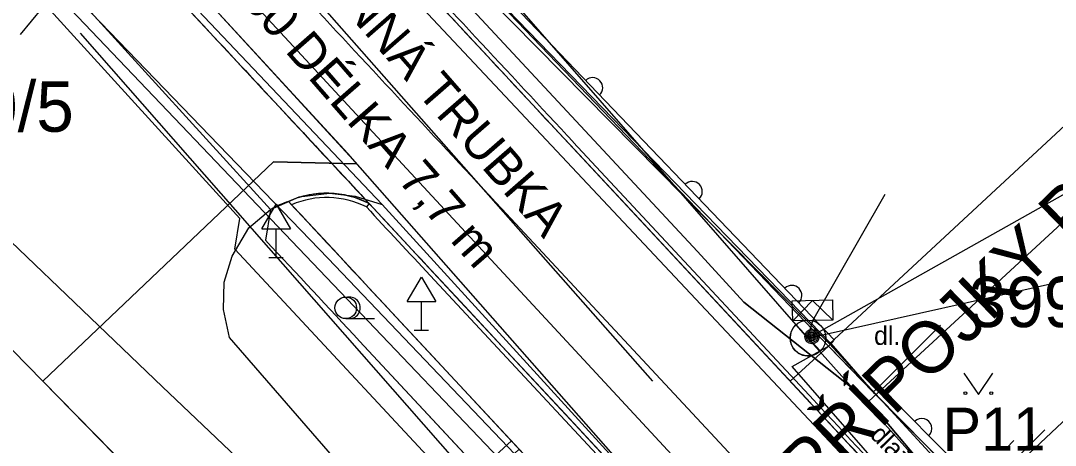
# Model space of a CAD drawing. Extents: x -643342 to -638635, y -1201752 to -1189948.
# Drawn here: x -639576.01 to -639540.06, y -1192560.69 to -1192545.93 of the extents above; entities that cross this region are included whole.
import ezdxf

# ---------------------------------------------------------------- set-up
doc = ezdxf.new("R2010")
doc.units = 0
for name, color, linetype in [('2', 7, 'Continuous'), ('42', 7, 'Continuous'), ('IS_EL_NN_NADZEMNÍ', 7, 'Continuous'), ('IS_EL_NN_PODZEMNÍ', 7, 'Continuous'), ('IS_PLYN_STL', 7, 'Continuous'), ('IS_TELEF_MISTNI_ZAMERENO', 7, 'Continuous'), ('IS_VODOVOD_VAS', 7, 'Continuous'), ('IS_VODOVOD_ZRUSENY', 7, 'Continuous'), ('K-HRANICE_KN', 7, 'Continuous'), ('K-ČÍSLA_PARCEL', 7, 'Continuous'), ('N-CHODNIK', 7, 'Continuous'), ('N-KAN_DEST_TRASA-NÁVRH', 7, 'Continuous'), ('N-OBVOD STAVBY 06', 7, 'Continuous'), ('N-OSA', 7, 'Continuous'), ('N-SILNICE', 7, 'Continuous'), ('N-SJEZDY', 7, 'Continuous'), ('N-SRAFY_PLOCHY', 7, 'Continuous'), ('N-SVAHOVÁNÍ', 7, 'Continuous'), ('tomaštík - Džuganovi - Vrstva 36', 7, 'Continuous'), ('Vrstva 46', 7, 'Continuous'), ('Z-hrany_a_čáry', 7, 'Continuous'), ('Z-popisy', 7, 'Continuous'), ('Z-sloupy', 7, 'Continuous'), ('Z-vchody_vjezdy', 7, 'Continuous'), ('Z-značky', 7, 'Continuous')]:
    doc.layers.add(name, color=color, linetype=linetype)

msp = doc.modelspace()

# ---------------------------------------------------------------- linework, layer by layer
at = {"layer": '42'}
msp.add_line((-639572.181, -1192537.888), (-639554.057, -1192558.462), dxfattribs=at)
at = {"layer": 'IS_EL_NN_NADZEMNÍ'}
for p, q in [((-639548.65, -1192556.96), (-639563.68, -1192539.76)), ((-639521.55, -1192587.25), (-639548.65, -1192556.96))]:
    msp.add_line(p, q, dxfattribs=at)
msp.add_lwpolyline([(-639547.781, -1192556.334), (-639549.18, -1192556.366), (-639549.196, -1192555.667), (-639547.797, -1192555.635)], close=True, dxfattribs=at)
for points in [[(-639547.781, -1192556.334), (-639548.496, -1192555.651), (-639549.18, -1192556.366)], [(-639549.063, -1192556.498), (-639548.222, -1192557.408)], [(-639548.222, -1192557.408), (-639549.063, -1192556.498)]]:
    msp.add_lwpolyline(points, dxfattribs=at)
msp.add_circle((-639548.65, -1192556.96), 0.62, dxfattribs=at)
for centre, radius, start, end in [((-639548.65, -1192556.96), 0.62, 131.8144, 312.7334), ((-639548.673, -1192556.986), 0.618, 315.9487, 316.8728)]:
    msp.add_arc(centre, radius, start, end, dxfattribs=at)
at = {"layer": 'IS_EL_NN_PODZEMNÍ'}
for p, q in [((-639548.65, -1192556.96), (-639533.97, -1192548.7)), ((-639548.48, -1192556.35), (-639545.97, -1192551.96)), ((-639548.65, -1192556.96), (-639532.15, -1192553.27)), ((-639548.65, -1192556.96), (-639548.48, -1192556.35))]:
    msp.add_line(p, q, dxfattribs=at)
at = {"layer": 'IS_PLYN_STL'}
msp.add_lwpolyline([(-639579.72, -1192550.39), (-639579.14, -1192550.94), (-639571.08, -1192558.66), (-639565.93, -1192563.54), (-639560.66, -1192567.58), (-639559.68, -1192568.38)], dxfattribs=at)
at = {"layer": 'IS_TELEF_MISTNI_ZAMERENO'}
for p, q in [((-639560.62, -1192545.22), (-639552.49, -1192553.95)), ((-639552.49, -1192553.95), (-639560.62, -1192545.22)), ((-639546.53, -1192559.15), (-639536.54, -1192549.92)), ((-639552.49, -1192553.95), (-639550.88, -1192555.71)), ((-639550.88, -1192555.71), (-639546.53, -1192559.15)), ((-639546.53, -1192559.15), (-639550.88, -1192555.71)), ((-639546.53, -1192559.15), (-639540.07, -1192566.82)), ((-639540.07, -1192566.82), (-639546.53, -1192559.15))]:
    msp.add_line(p, q, dxfattribs=at)
at = {"layer": 'IS_VODOVOD_VAS'}
for points in [[(-639574.178, -1192545), (-639565.32, -1192554.2), (-639544.196, -1192576.345), (-639543.991, -1192576.56), (-639543.73, -1192576.83), (-639534.504, -1192586.506), (-639531.24, -1192590.494), (-639527.133, -1192595.51), (-639522.796, -1192601.597), (-639522.77, -1192601.637), (-639518.91, -1192607.22), (-639515.881, -1192615.376)], [(-639575.085, -1192545.333), (-639575.259, -1192545.488), (-639576.018, -1192546.41)], [(-639574.504, -1192545.287), (-639565.62, -1192554.6), (-639534.876, -1192586.834), (-639527.527, -1192595.81), (-639523.229, -1192601.871), (-639519.29, -1192607.54), (-639519.07, -1192608.24), (-639516.818, -1192614.307), (-639515.63, -1192618.18), (-639513.05, -1192632.38), (-639511.6, -1192653.11)]]:
    msp.add_lwpolyline(points, dxfattribs=at)
at = {"layer": 'IS_VODOVOD_ZRUSENY'}
msp.add_lwpolyline([(-639573.944, -1192546.368), (-639550.08, -1192573.56), (-639545.32, -1192575.03), (-639544.04, -1192576.59), (-639530.53, -1192590.38), (-639522.03, -1192601.36), (-639515.23, -1192614.43)], dxfattribs=at)
at = {"layer": 'K-HRANICE_KN'}
for p, q in [((-639564.643, -1192550.549), (-639574.559, -1192539.749)), ((-639574.559, -1192539.749), (-639564.324, -1192550.911)), ((-639564.643, -1192550.549), (-639574.559, -1192539.749)), ((-639547.9, -1192557.16), (-639564.74, -1192540.08)), ((-639547.9, -1192557.16), (-639537.05, -1192547.08)), ((-639583.2, -1192550.31), (-639575.24, -1192558.46)), ((-639575.24, -1192558.46), (-639583.197, -1192550.313)), ((-639524.691, -1192595.875), (-639564.643, -1192550.549)), ((-639524.691, -1192595.875), (-639564.643, -1192550.549)), ((-639575.24, -1192558.46), (-639567.217, -1192550.837)), ((-639567.217, -1192550.837), (-639575.24, -1192558.46)), ((-639575.24, -1192558.46), (-639567.217, -1192550.837)), ((-639564.324, -1192550.911), (-639567.217, -1192550.837)), ((-639567.217, -1192550.837), (-639564.324, -1192550.911)), ((-639542.8, -1192562.7), (-639532.09, -1192552.6)), ((-639542.8, -1192562.7), (-639547.9, -1192557.16)), ((-639561.72, -1192572.25), (-639575.24, -1192558.46)), ((-639562.65, -1192571.27), (-639575.24, -1192558.46))]:
    msp.add_line(p, q, dxfattribs=at)
at = {"layer": 'N-CHODNIK'}
for p, q in [((-639547.94, -1192557.24), (-639564.59, -1192539.87)), ((-639563.902, -1192552.283), (-639563.994, -1192552.405)), ((-639563.132, -1192556.044), (-639554.775, -1192565.016)), ((-639547.94, -1192557.24), (-639549.267, -1192558.458)), ((-639549.267, -1192558.458), (-639547.94, -1192557.24)), ((-639546.38, -1192558.84), (-639547.94, -1192557.24)), ((-639542.746, -1192562.497), (-639546.38, -1192558.84))]:
    msp.add_line(p, q, dxfattribs=at)
for centre, radius, start, end in [((-639565.377, -1192555.154), 3.227, 62.8122, 114.2453), ((-639565.377, -1192555.154), 3.077, 63.2943, 113.2968), ((-632043.168, -1185549.151), 10278.444, 222.9480255, 222.977221)]:
    msp.add_arc(centre, radius, start, end, dxfattribs=at)
at = {"layer": 'N-KAN_DEST_TRASA-NÁVRH'}
msp.add_lwpolyline([(-639583.962, -1192528.01), (-639550.452, -1192564.184), (-639529.583, -1192588.026), (-639514.491, -1192612.048), (-639507.737, -1192644.326), (-639498.832, -1192694.254), (-639511.439, -1192713.331), (-639516.613, -1192716.507), (-639553.938, -1192703.739), (-639570.485, -1192701.616), (-639578.687, -1192703.18)], dxfattribs=at)
at = {"layer": 'N-OBVOD STAVBY 06'}
for points in [[(-639580.824, -1192520.961), (-639575.028, -1192527.69), (-639575.555, -1192528.126), (-639571.584, -1192532.34), (-639569.898, -1192532.101), (-639567.334, -1192531.011), (-639562.714, -1192535.496), (-639563.777, -1192537.334), (-639563.916, -1192537.749), (-639564.117, -1192538.572), (-639564.127, -1192539.047), (-639564.59, -1192539.87), (-639556.157, -1192548.58), (-639547.851, -1192557.152), (-639546.37, -1192558.85), (-639546.295, -1192558.925), (-639542.755, -1192562.507)], [(-639532.853, -1192592.991), (-639532.948, -1192593.015), (-639536.515, -1192588.213), (-639537.119, -1192588.308), (-639546.267, -1192578.054), (-639553.229, -1192570.356), (-639556.749, -1192566.564), (-639568.569, -1192553.875), (-639568.389, -1192552.802), (-639591.813, -1192527.078)]]:
    msp.add_lwpolyline(points, dxfattribs=at)
at = {"layer": 'N-OSA'}
msp.add_lwpolyline([(-639550.934, -1192561.438), (-639559.291, -1192552.466)], dxfattribs=at)
msp.add_arc((-632042.643, -1185548.663), 10273.911, 222.9214561, 222.9772243, dxfattribs=at)
at = {"layer": 'N-SILNICE'}
for p, q in [((-639556.912, -1192550.251), (-639548.555, -1192559.223)), ((-639548.557, -1192559.221), (-639556.912, -1192550.251)), ((-639556.803, -1192550.149), (-639548.446, -1192559.12)), ((-639561.778, -1192554.784), (-639553.421, -1192563.755)), ((-639561.669, -1192554.681), (-639553.312, -1192563.653))]:
    msp.add_line(p, q, dxfattribs=at)
for centre, radius, start, end in [((-632043.168, -1185549.151), 10269.944, 222.9214551, 222.977221), ((-632042.268, -1185548.314), 10271.173, 222.9214572, 222.9772255), ((-632043.168, -1185549.151), 10269.794, 222.9214551, 222.977221), ((-635904.087, -1189140.863), 5003.201, 222.848207, 222.911144), ((-632043.168, -1185549.151), 10276.444, 222.9214551, 222.977221), ((-632043.168, -1185549.151), 10276.594, 222.9591018, 222.977221), ((-640272.452, -1193234.69), 990.092, 42.727797, 43.018095), ((-640272.828, -1193235.039), 990.605, 42.727709, 43.018008), ((-640272.452, -1193234.69), 990.242, 42.727797, 43.018095)]:
    msp.add_arc(centre, radius, start, end, dxfattribs=at)
at = {"layer": 'N-SJEZDY'}
msp.add_line((-639590.66, -1192526.86), (-639567.322, -1192552.488), dxfattribs=at)
msp.add_arc((-639565.694, -1192555.36), 3.301, 107.7054, 119.5413, dxfattribs=at)
at = {"layer": 'N-SRAFY_PLOCHY'}
for p, q in [((-639590.66, -1192526.86), (-639567.322, -1192552.488)), ((-639547.94, -1192557.24), (-639564.59, -1192539.87)), ((-639564.321, -1192542.291), (-639549.267, -1192558.458)), ((-639560.26, -1192546.656), (-639562.97, -1192543.744)), ((-639571.626, -1192543.976), (-639568.484, -1192547.359)), ((-639557.448, -1192549.676), (-639560.26, -1192546.656)), ((-639568.484, -1192547.359), (-639565.903, -1192550.134)), ((-639554.83, -1192552.487), (-639557.448, -1192549.676)), ((-639565.903, -1192550.134), (-639564.458, -1192551.687)), ((-639564.458, -1192551.687), (-639563.902, -1192552.283)), ((-639563.902, -1192552.283), (-639561.669, -1192554.681)), ((-639567.322, -1192552.488), (-639567.501, -1192553.555)), ((-639552.339, -1192555.161), (-639554.83, -1192552.487)), ((-639561.669, -1192554.681), (-639559.26, -1192557.267)), ((-639549.746, -1192557.945), (-639552.339, -1192555.161)), ((-639559.26, -1192557.267), (-639557.091, -1192559.596)), ((-639549.267, -1192558.458), (-639547.94, -1192557.24)), ((-639547.94, -1192557.24), (-639549.267, -1192558.458)), ((-639545.874, -1192559.349), (-639547.94, -1192557.24)), ((-639548.34, -1192559.453), (-639549.746, -1192557.945)), ((-639549.267, -1192558.458), (-639547.377, -1192560.488)), ((-639557.091, -1192559.596), (-639554.895, -1192561.953)), ((-639546.684, -1192561.234), (-639548.34, -1192559.453)), ((-639544.493, -1192560.739), (-639545.874, -1192559.349)), ((-639547.377, -1192560.488), (-639545.693, -1192562.303))]:
    msp.add_line(p, q, dxfattribs=at)
for points in [[(-639568.484, -1192547.36), (-639568.484, -1192547.359)], [(-639555.552, -1192561.248), (-639557.481, -1192559.177), (-639559.113, -1192557.425), (-639560.725, -1192555.695), (-639562.255, -1192554.052), (-639563.126, -1192553.117), (-639563.902, -1192552.283), (-639564.367, -1192552.089), (-639564.863, -1192551.968), (-639565.206, -1192551.931), (-639565.605, -1192551.935), (-639565.987, -1192551.985), (-639566.426, -1192552.102), (-639566.702, -1192552.211), (-639565.326, -1192553.69), (-639563.897, -1192555.223), (-639561.821, -1192557.452), (-639558.007, -1192561.546)], [(-639566.698, -1192552.215), (-639566.702, -1192552.211)], [(-639564.23, -1192557.067), (-639559.779, -1192561.845), (-639558.681, -1192560.823), (-639563.133, -1192556.044)]]:
    msp.add_lwpolyline(points, dxfattribs=at)
for centre, radius, start, end in [((-635904.087, -1189140.863), 5003.201, 222.848207, 222.911144), ((-632043.168, -1185549.151), 10276.444, 222.9214551, 222.9589536), ((-639565.377, -1192555.154), 3.227, 62.8122, 114.2453), ((-639565.694, -1192555.36), 3.301, 107.7054, 119.5413), ((-639565.694, -1192555.36), 3.301, 107.7054, 119.5413), ((-632043.168, -1185549.151), 10278.444, 222.948054, 222.9772188), ((-632043.421, -1185549.387), 10279.598, 222.9504707, 222.9772219)]:
    msp.add_arc(centre, radius, start, end, dxfattribs=at)
at = {"layer": 'N-SVAHOVÁNÍ'}
msp.add_line((-639559.503, -1192561.042), (-639558.954, -1192560.53), dxfattribs=at)
for points in [[(-639567.322, -1192552.488), (-639567.501, -1192553.555)], [(-639555.869, -1192566.043), (-639564.23, -1192557.067)]]:
    msp.add_lwpolyline(points, dxfattribs=at)
msp.add_arc((-632043.421, -1185549.387), 10279.598, 222.9504707, 222.9772219, dxfattribs=at)
at = {"layer": 'Z-hrany_a_čáry'}
for p, q in [((-639547.94, -1192557.24), (-639564.59, -1192539.87)), ((-639547.723, -1192557.032), (-639564.219, -1192539.823)), ((-639543.49, -1192565.25), (-639564.61, -1192542.75)), ((-639563.45, -1192552.32), (-639570.98, -1192544.37)), ((-639567.322, -1192552.488), (-639566.332, -1192552.055)), ((-639566.332, -1192552.055), (-639565.272, -1192551.929)), ((-639565.272, -1192551.929), (-639564.378, -1192552.027)), ((-639564.378, -1192552.027), (-639563.45, -1192552.32)), ((-639548.17, -1192569.06), (-639563.45, -1192552.32)), ((-639568.08, -1192553.13), (-639567.322, -1192552.488)), ((-639568.661, -1192554.11), (-639568.08, -1192553.13)), ((-639568.94, -1192555.018), (-639568.661, -1192554.11)), ((-639568.954, -1192555.968), (-639568.94, -1192555.018)), ((-639568.75, -1192556.94), (-639568.954, -1192555.968)), ((-639544.043, -1192556.51), (-639546.168, -1192558.628)), ((-639563.6, -1192562.86), (-639568.75, -1192556.94)), ((-639549.2, -1192557.95), (-639547.94, -1192557.24)), ((-639544.03, -1192563.85), (-639549.2, -1192557.95)), ((-639546.168, -1192558.628), (-639546.38, -1192558.84)), ((-639546.38, -1192558.84), (-639543.39, -1192561.84)), ((-639543.178, -1192561.628), (-639546.168, -1192558.628)), ((-639540.419, -1192560.146), (-639542.35, -1192562.07))]:
    msp.add_line(p, q, dxfattribs=at)
for centre, start, end in [((-639556.131, -1192548.261), 313.7881, 133.7881), ((-639552.671, -1192551.87), 313.7881, 133.7881), ((-639549.211, -1192555.48), 313.7881, 133.7881), ((-639544.696, -1192560.105), 314.9043, 134.9043)]:
    msp.add_arc(centre, 0.35, start, end, dxfattribs=at)
at = {"layer": 'Z-sloupy'}
for radius in [0.25, 0.2, 0.15, 0.1, 0.05]:
    msp.add_circle((-639548.51, -1192556.91), radius, dxfattribs=at)
at = {"layer": 'Z-vchody_vjezdy'}
for p, q in [((-639547.761, -1192557.065), (-639547.94, -1192557.24)), ((-639547.94, -1192557.24), (-639546.38, -1192558.84)), ((-639546.201, -1192558.665), (-639546.38, -1192558.84))]:
    msp.add_line(p, q, dxfattribs=at)
at = {"layer": 'Z-značky'}
for p, q in [((-639567.63, -1192553.16), (-639567.13, -1192552.31)), ((-639567.13, -1192552.31), (-639566.63, -1192553.16)), ((-639567.63, -1192553.16), (-639566.63, -1192553.16)), ((-639567.13, -1192554.16), (-639567.13, -1192553.16)), ((-639567.38, -1192554.16), (-639566.88, -1192554.16)), ((-639562.58, -1192555.69), (-639562.08, -1192554.84)), ((-639562.08, -1192554.84), (-639561.58, -1192555.69)), ((-639562.58, -1192555.69), (-639561.58, -1192555.69)), ((-639562.08, -1192556.69), (-639562.08, -1192555.69)), ((-639564.711, -1192556.285), (-639563.711, -1192556.285)), ((-639562.33, -1192556.69), (-639561.83, -1192556.69)), ((-639543.229, -1192558.177), (-639542.729, -1192558.927)), ((-639542.729, -1192558.927), (-639542.229, -1192558.177)), ((-639541.747, -1192560.79), (-639541.492, -1192560.525))]:
    msp.add_line(p, q, dxfattribs=at)
for centre, radius in [((-639564.711, -1192555.91), 0.375), ((-639543.179, -1192558.877), 0.05), ((-639542.28, -1192558.877), 0.05)]:
    msp.add_circle(centre, radius, dxfattribs=at)
msp.add_arc((-639564.586, -1192555.91), 0.375, 260.4059, 99.5941, dxfattribs=at)

# ---------------------------------------------------------------- texts
at = {"layer": '2'}
msp.add_text('PŘELOŽKA STL PŘÍPOJKY P1', height=1.8, rotation=44.2309, dxfattribs=at).set_placement((-639561.865, -1192575.458))
at = {"layer": 'K-ČÍSLA_PARCEL'}
for s, p in [('390/5', (-639580.016, -1192549.791)), ('390/5', (-639580.016, -1192549.791)), ('399', (-639543.063, -1192556.58))]:
    msp.add_text(s, height=1.75, dxfattribs=at).set_placement(p)
at = {"layer": 'tomaštík - Džuganovi - Vrstva 36'}
for s, p in [('OCHRANNÁ TRUBKA ', (-639568.872, -1192540.866)), ('PE 160 DÉLKA 7,7 m', (-639570.756, -1192542.509))]:
    msp.add_text(s, height=1.25, rotation=311.0908, dxfattribs=at).set_placement(p)
at = {"layer": 'Vrstva 46'}
msp.add_text('P11', height=1.5, rotation=0.301, dxfattribs=at).set_placement((-639543.968, -1192560.884))
at = {"layer": 'Z-popisy'}
msp.add_text('dl.', height=0.65, dxfattribs=at).set_placement((-639546.354, -1192557.198))
msp.add_text('dlažba', height=0.65, rotation=314.5232, dxfattribs=at).set_placement((-639546.528, -1192560.36))

doc.saveas('drawing.dxf')
